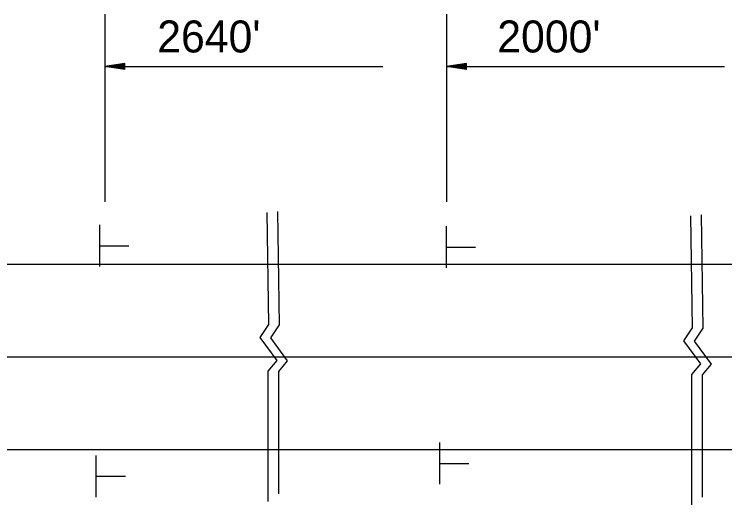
# Model space of a CAD drawing. Extents: x -500 to 213, y 382723 to 382830.
# Drawn here: x -270.38 to -257.04, y 382796.29 to 382805.5 of the extents above; entities that cross this region are included whole.
import ezdxf

# ---------------------------------------------------------------- set-up
doc = ezdxf.new("R2010")
doc.units = 0
doc.layers.add('Default', color=7, linetype='Continuous')

msp = doc.modelspace()

# ---------------------------------------------------------------- linework, layer by layer
at = {"layer": 'Default'}
for p, q in [((-268.682, 382805.499), (-268.682, 382801.978)), ((-262.266, 382805.499), (-262.266, 382801.978)), ((-268.307, 382804.576), (-268.682, 382804.52)), ((-268.682, 382804.52), (-263.463, 382804.52)), ((-268.307, 382804.464), (-268.682, 382804.52)), ((-268.307, 382804.567), (-268.62, 382804.52)), ((-268.307, 382804.473), (-268.62, 382804.52)), ((-268.307, 382804.557), (-268.555, 382804.52)), ((-268.307, 382804.482), (-268.555, 382804.52)), ((-268.307, 382804.548), (-268.493, 382804.52)), ((-268.307, 382804.492), (-268.493, 382804.52)), ((-268.307, 382804.538), (-268.429, 382804.52)), ((-268.307, 382804.502), (-268.429, 382804.52)), ((-268.307, 382804.529), (-268.366, 382804.52)), ((-268.307, 382804.511), (-268.366, 382804.52)), ((-268.307, 382804.464), (-268.307, 382804.576)), ((-261.891, 382804.576), (-262.266, 382804.52)), ((-262.266, 382804.52), (-257.047, 382804.52)), ((-261.891, 382804.464), (-262.266, 382804.52)), ((-261.891, 382804.567), (-262.203, 382804.52)), ((-261.891, 382804.473), (-262.203, 382804.52)), ((-261.891, 382804.557), (-262.139, 382804.52)), ((-261.891, 382804.482), (-262.139, 382804.52)), ((-261.891, 382804.548), (-262.077, 382804.52)), ((-261.891, 382804.492), (-262.077, 382804.52)), ((-261.891, 382804.538), (-262.013, 382804.52)), ((-261.891, 382804.502), (-262.013, 382804.52)), ((-261.891, 382804.529), (-261.95, 382804.52)), ((-261.891, 382804.511), (-261.95, 382804.52)), ((-261.891, 382804.464), (-261.891, 382804.576)), ((-268.773, 382800.764), (-268.773, 382801.547)), ((-262.266, 382800.741), (-262.266, 382801.523)), ((-268.762, 382801.153), (-268.228, 382801.153)), ((-262.255, 382801.13), (-261.721, 382801.13)), ((-272.48, 382800.808), (-266.283, 382800.808)), ((-266.283, 382800.808), (-260.198, 382800.808)), ((-260.198, 382800.808), (-251.538, 382800.808)), ((-272.434, 382799.07), (-266.317, 382799.07)), ((-266.317, 382799.07), (-260.198, 382799.07)), ((-260.198, 382799.07), (-251.538, 382799.07)), ((-262.392, 382796.676), (-262.392, 382797.459)), ((-272.388, 382797.331), (-266.351, 382797.331)), ((-266.351, 382797.331), (-258.916, 382797.331)), ((-260.198, 382797.331), (-250.621, 382797.331)), ((-268.841, 382796.438), (-268.841, 382797.22)), ((-262.381, 382797.065), (-261.847, 382797.065)), ((-268.829, 382796.827), (-268.295, 382796.827))]:
    msp.add_line(p, q, dxfattribs=at)
for points in [[(-265.641, 382801.779), (-265.608, 382799.675), (-265.771, 382799.434), (-265.454, 382799.001), (-265.621, 382798.801), (-265.621, 382796.355)], [(-265.441, 382801.798), (-265.409, 382799.667), (-265.571, 382799.425), (-265.255, 382798.992), (-265.421, 382798.793), (-265.422, 382796.496)], [(-257.684, 382801.716), (-257.652, 382799.612), (-257.814, 382799.371), (-257.498, 382798.938), (-257.665, 382798.738), (-257.665, 382796.292)], [(-257.485, 382801.735), (-257.452, 382799.604), (-257.615, 382799.362), (-257.298, 382798.929), (-257.465, 382798.729), (-257.465, 382796.433)]]:
    msp.add_lwpolyline(points, dxfattribs=at)

# ---------------------------------------------------------------- texts
for s, p in [("2640'", (-267.697, 382804.781)), ("2000'", (-261.313, 382804.781))]:
    msp.add_text(s, height=0.6, dxfattribs=at).set_placement(p)

doc.saveas('drawing.dxf')
